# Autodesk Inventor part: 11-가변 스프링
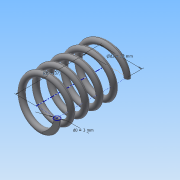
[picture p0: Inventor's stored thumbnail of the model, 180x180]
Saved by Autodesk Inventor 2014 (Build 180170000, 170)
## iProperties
Created: 2015-09
Part Number: 11-가변 스프링
Material: 강철, 탄소
Document SubType Name: Modeling
Designer: study
Density: 1 g/cm^3
Appearance: 반연마
Mass: 2.36745 g
Surface Area: 32.4192 cm^2
Volume: 2.36745 cm^3
Author: study
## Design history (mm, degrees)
sketch "스케치1"
  geometry: L1 (0, 0)-(11, 0); L2 (11, 0)-(11, 25.358); L3 (11, 25.358)-(0, 25.358); L4 (0, 25.358)-(0, 0); C1 r 1.5 at (11, 0)
  constraints: 8 end point, 2 parallel, 1 centre point, 1 coincident, 1 horizontal, 1 perpendicular
  dimensions: "d0" = 3 diameter of C1; "d1" = 25.35829 distance of L3.end L1.start (derived); "d2" = 22 diameter of L2 L4
feature "코일1" sketch "스케치1" pitch "d3" = 10; turns "d5" = 5; dims "d4" = 25.35829 (= d1), "d6" = 0, angle "d7" = 90 deg, angle "d8" = 90 deg, "d9" = 0, "d10" = 0
sketch "스케치2"
  geometry: L1 (-12.5, 0)-(-9.5, 0) reference; 1 further point
  constraints: 1 horizontal alignment
extrude "돌출1" cut sketch "스케치2" stored distance "d11" = 10; taper "d12" = 0 deg
node "작업 평면1"
sketch "스케치3"
  geometry: L1 (-9.5, 0)-(-12.5, 0) reference; 1 further point
  constraints: 1 horizontal alignment
extrude "돌출2" cut sketch "스케치3" stored distance "d14" = 10; taper "d15" = 0 deg
node "솔리드1"
node "절단 모서리 투영1"
node "절단 모서리 투영2"
other parameters: "d13" = 25.35829 (= d1)
